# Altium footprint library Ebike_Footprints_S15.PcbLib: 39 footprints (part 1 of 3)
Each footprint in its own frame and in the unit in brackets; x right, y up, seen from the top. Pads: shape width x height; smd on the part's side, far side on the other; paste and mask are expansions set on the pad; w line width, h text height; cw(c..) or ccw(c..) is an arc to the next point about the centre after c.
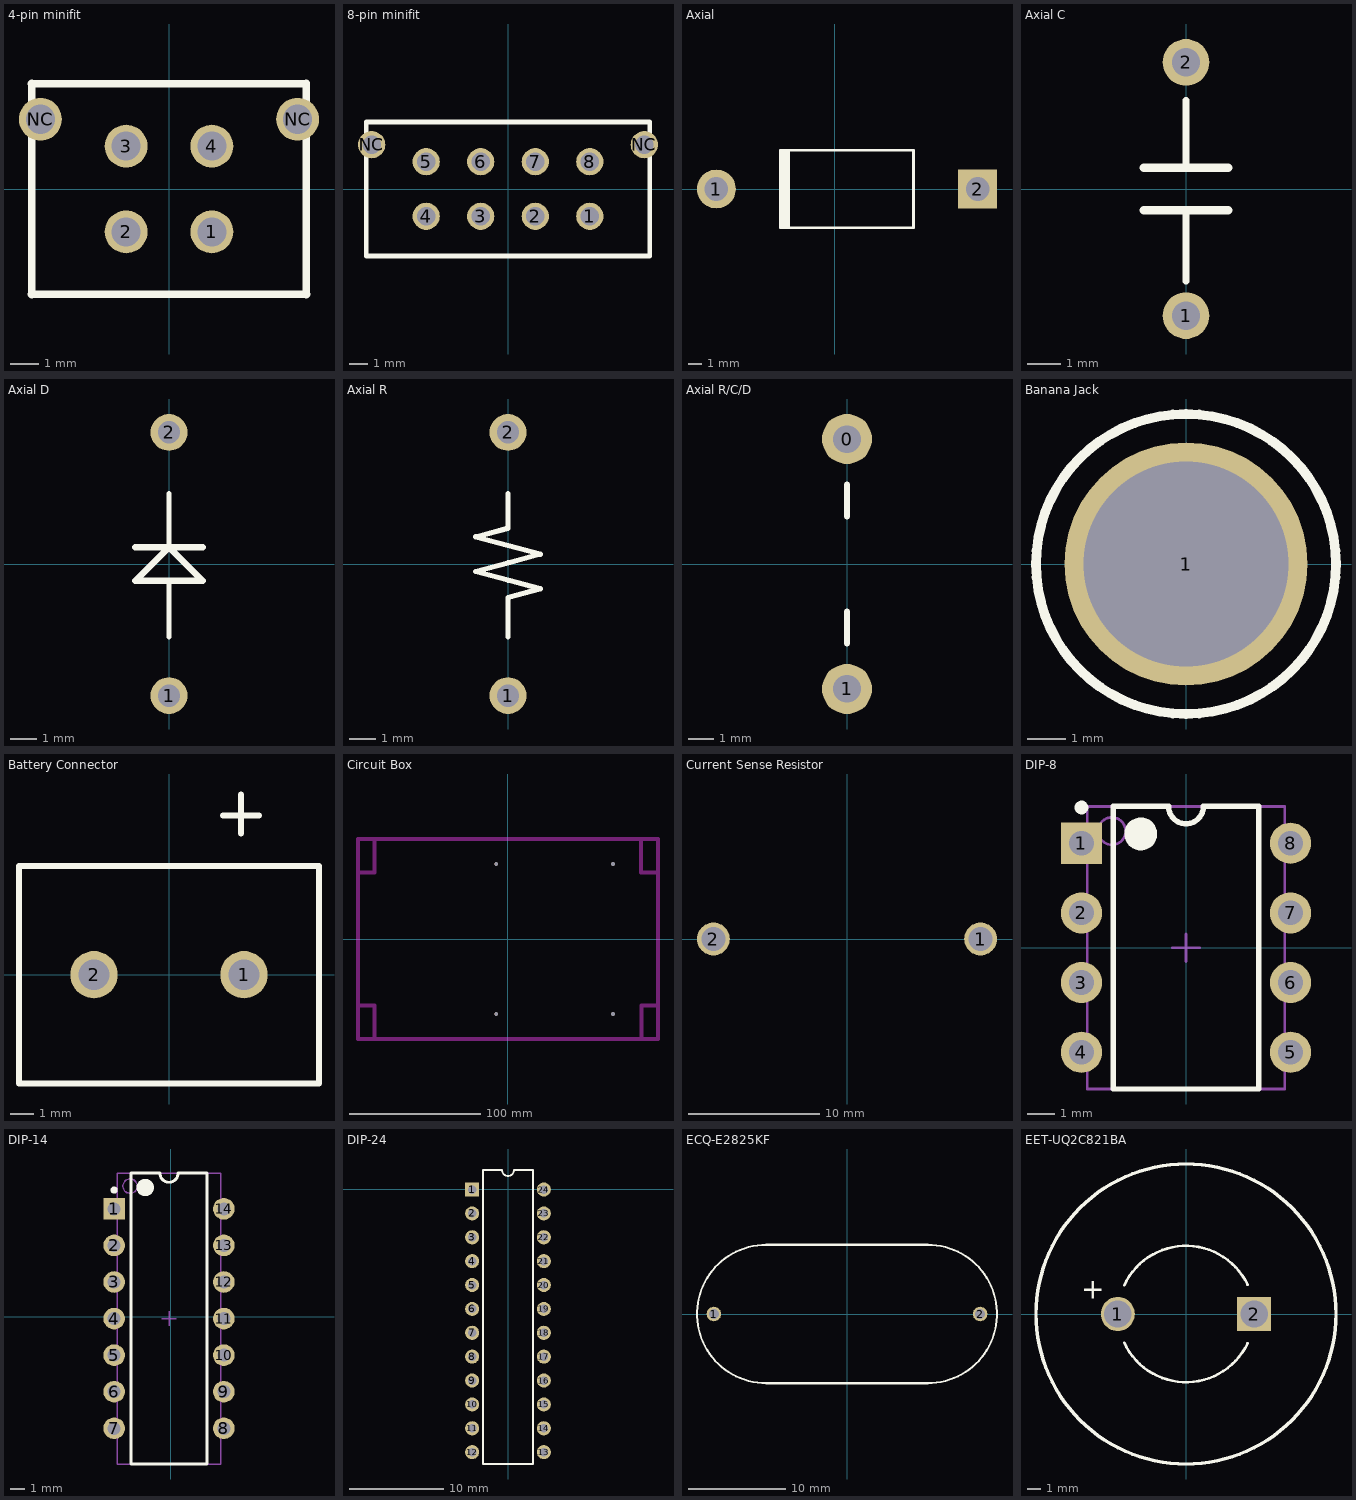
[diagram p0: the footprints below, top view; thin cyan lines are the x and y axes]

## 4-pin minifit [mm] "538-43045-0412   board connector straight"
pads (6):
  round 1.5 hole 1.02: 1(1.5,-1.5) 2(-1.5,-1.5) 3(-1.5,1.5) 4(1.5,1.5) NC(-4.5,2.44) NC(4.5,2.44)
Top Overlay:
  lines w0.254: -4.826,-3.683 4.826,-3.683 ; -4.826,3.683 4.699,3.683 ; -4.8,-3.7 -4.8,3.7 ; 4.8,-3.7 4.8,3.7
3D body: height 9.91, standoff 0, extent -4.826,-3.683 4.826,3.683

## 8-pin minifit [mm] "538-43045-0812   board connector straight"
pads (10):
  round 1.5 hole 1.02: 1(4.5,-1.5) 2(1.5,-1.5) 3(-1.5,-1.5) 4(-4.5,-1.5) 5(-4.5,1.5) 6(-1.5,1.5) 7(1.5,1.5) 8(4.5,1.5) NC(-7.5,2.44) NC(7.5,2.44)
Top Overlay:
  lines w0.254: -7.8,-3.7 -7.8,3.7 ; -7.747,-3.683 7.747,-3.683 ; -7.747,3.683 7.747,3.683 ; 7.8,-3.7 7.8,3.7
3D body: height 9.91, standoff 0, extent -7.747,-3.683 7.747,3.683

## Axial [mm]
pads (2):
  round 2.8 hole 1.7: 1(-8.531,0)
  rect 2.8x2.8 hole 1.7: 2(10.309,0)
Top Overlay:
  region: -3.211,2.8 -4.011,2.8 -4.011,-2.8 -3.211,-2.8
  lines w0.2: -3.911,-2.8 5.689,-2.8 5.689,2.8 -3.911,2.8

## Axial C [mm]
pads (2):
  round 1.4 hole 0.85: 1(0,-3.81) 2(0,3.81)
Top Overlay:
  lines w0.2: 0,-2.769 0,-0.635 ; 0,0.635 0,2.667
  lines w0.254: -1.27,-0.635 1.27,-0.635 ; -1.27,0.635 1.27,0.635
3D body: height 5, standoff -3, extent -1.116,-2.54 1.143,2.937

## Axial D [mm]
pads (2):
  round 1.4 hole 0.85: 1(0,-5) 2(0,5)
Top Overlay:
  lines w0.2: 0,-2.769 0,-0.635 ; 0,0.635 0,2.667
  lines w0.254: -1.27,0.635 1.27,0.635 ; -1.27,-0.635 1.27,-0.635 0,0.635 -1.27,-0.635
3D body: height 2.73, standoff -2.6, extent -1.343,-5.512 1.397,5.512

## Axial R [mm]
pads (2):
  round 1.4 hole 0.85: 1(0,-5) 2(0,5)
Top Overlay:
  lines w0.2: 0,-2.769 0,-1.27 1.227,-0.941 0,-0.613 -1.227,-0.284 0,0.045 1.227,0.373 0,0.702 -1.227,1.031 0,1.36 0,2.667
3D body: height 3.25, standoff -0.65, extent -1.27,-5.497 1.23,5.497

## Axial R/C/D [mm] "Through-Hole FootPrint"
pads (2):
  round 2 hole 1.1: 0(0,5) 1(0,-5)
Top Overlay:
  lines w0.254: 0,-3.175 0,-1.905 ; 0,1.905 0,3.175

## Banana Jack [mm] "575-8"
pads (1):
  round 6.4 hole 5.4: 1(0,0)
Top Overlay:
  circle w0.254: c0,0 r3.95
3D body: height 2.47, standoff 0.1, extent -2.59,-2.65 2.59,2.54
3D body: height 2.46, standoff 0.1, extent -3.932,-3.947 3.937,3.937
3D body: height 9, standoff 0.1, extent -2.59,-2.667 2.59,2.523

## Battery Connector [mm] "Phoenix 2-terminal Block Screw connector"
pads (2):
  round 2 hole 1.3: 1(3.175,0) 2(-3.175,0)
Top Overlay:
  lines w0.254: -6.35,-4.572 -6.35,4.572 ; -6.345,-4.6 6.345,-4.6 ; -6.345,4.6 6.345,4.6 ; 2.286,6.731 3.81,6.731 ; 3.048,5.969 3.048,7.62 ; 6.35,-4.572 6.35,4.572
3D body: height 15.2, standoff -3.5, extent -5,-4.301 5,4.699

## Circuit Box [mil] "Ebike mounted circuit box"
via 3155,-2255 diameter 118.11 hole 118.11
via 3155,2245 diameter 118.11 hole 118.11
via -350.39,2250 diameter 118.11 hole 118.11
via -350.39,-2250 diameter 118.11 hole 118.11
Keep-Out Layer:
  lines w118.11: -4500,-2000 -4000,-2000 -4000,-3000 ; -4500,2000 -4000,2000 -4000,3000 ; 4000,3000 4000,2000 4500,2000 ; 4005,-3000 4005,-2000 4505,-2000 ; 4500,2990 4500,-3000 -4500,-3000 -4500,3000 4500,3000
3D body: height 1062.99, standoff 0, extent 4455,-3020 4495,3015
3D body: height 1062.99, standoff 0, extent -4475,-3020 -4435,3015
3D body: height 1062.99, standoff 0, extent -4460,-3020 4475,-2980
3D body: height 1062.99, standoff 0, extent -4460,2975 4475,3015
3D body: height 1062.99, standoff 984.25, extent -4460,-3000 4475,2990

## Current Sense Resistor [mm] "Current Sense Resistor OAR5"
height 22.4
pads (2):
  round 2.5 hole 1.8: 1(10.16,0) 2(-10.16,0)

## DIP-8 [mm] "DIP; 8 Leads; Row Spacing 7.62 mm; Pitch 2.54 mm"
height 5.08
pads (8):
  rect 1.5x1.5 hole 0.9: 1(-3.81,3.81)
  round 1.5 hole 0.9: 2(-3.81,1.27) 3(-3.81,-1.27) 4(-3.81,-3.81) 5(3.81,-3.81) 6(3.81,-1.27) 7(3.81,1.27) 8(3.81,3.81)
Top Overlay:
  circle w0.6: c-1.65,4.15 r0.3
  circle w0.25: c-3.81,5.11 r0.125
  lines w0.2: -2.65,-5.15 2.65,-5.15 2.65,5.15 0.635,5.15 cw(c0,5.15) -0.635,5.15 -2.65,5.15 -2.65,-5.15
Mechanical 13:
  circle w0.1: c-2.7,4.25 r0.5
  lines w0.1: -3.6,-5.15 3.6,-5.15 3.6,5.15 -3.6,5.15 -3.6,-5.15
Mechanical 15:
  lines w0.1: -0.5,0 0.5,0 ; 0,-0.5 0,0.5
3D body: height 5.08, standoff 0, extent -3.6,-5.15 3.6,5.15

## DIP-14 [mm]
pads (14):
  rect 1.5x1.5 hole 0.9: 1(-3.937,7.493)
  round 1.5 hole 0.9: 2(-3.937,4.953) 3(-3.937,2.413) 4(-3.937,-0.127) 5(-3.937,-2.667) 6(-3.937,-5.207) 7(-3.937,-7.747) 8(3.683,-7.747) 9(3.683,-5.207) 10(3.683,-2.667) 11(3.683,-0.127) 12(3.683,2.413) 13(3.683,4.953) 14(3.683,7.493)
Top Overlay:
  circle w0.6: c-1.777,8.973 r0.3
  circle w0.25: c-3.937,8.793 r0.125
  lines w0.2: -2.777,-10.227 2.523,-10.227 2.523,9.973 0.508,9.973 cw(c-0.127,9.973) -0.762,9.973 -2.777,9.973 -2.777,-10.227
Mechanical 13:
  circle w0.1: c-2.827,9.073 r0.5
  lines w0.1: -3.727,-10.227 3.473,-10.227 3.473,9.973 -3.727,9.973 -3.727,-10.227
Mechanical 15:
  lines w0.1: -0.627,-0.127 0.373,-0.127 ; -0.127,-0.627 -0.127,0.373
3D body: height 5.08, standoff 0, extent -3.727,-10.227 3.473,9.973

## DIP-24 [mm]
pads (24):
  rect 1.5x1.5 hole 0.9: 1(-3.81,-0.01)
  round 1.5 hole 0.9: 2(-3.81,-2.55) 3(-3.81,-5.09) 4(-3.81,-7.63) 5(-3.81,-10.17) 6(-3.81,-12.71) 7(-3.81,-15.25) 8(-3.81,-17.79) 9(-3.81,-20.33) 10(-3.81,-22.87) 11(-3.81,-25.41) 12(-3.81,-27.95) 13(3.81,-27.95) 14(3.81,-25.41) 15(3.81,-22.87) 16(3.81,-20.33) 17(3.81,-17.79) 18(3.81,-15.25) 19(3.81,-12.71) 20(3.81,-10.17) 21(3.81,-7.63) 22(3.81,-5.09) 23(3.81,-2.55) 24(3.81,-0.01)
Top Overlay:
  lines w0.2: -2.667,-29.21 2.633,-29.21 ; -2.65,-29.21 -2.65,2.07 -0.635,2.07 ccw(c0,2.07) 0.635,2.07 2.65,2.07 2.65,-29.21
3D body: height 1.75, standoff 0.1, extent -3.683,-29.337 3.683,1.992

## ECQ-E2825KF [mm] "Thin Film Cap, 8.2uF 250V"
pads (2):
  round 1.5 hole 1: 1(-13.75,0) 2(13.75,0)
Top Overlay:
  lines w0.2: -8.35,-7.15 cw(c-8.35,0) -8.35,7.15 ; 8.35,-7.15 ccw(c8.35,0) 8.35,7.15
  lines w0.254: -8.35,-7.15 8.35,-7.15 ; -8.35,7.15 8.35,7.15
3D body: height 25, standoff 1.5, extent -8.382,-7.112 8.392,7.263
3D body: height 25, standoff 1.5, extent 1.27,-7.112 15.514,7.16
3D body: height 25, standoff 1.5, extent -15.621,-7.136 -1.377,7.136

## EET-UQ2C821BA [mm] "Electrolytic Cap"
pads (2):
  round 2.5 hole 2: 1(-5,0)
  rect 2.5x2.5 hole 2: 2(5,0)
Top Overlay:
  circle w0.254: c0,0 r11
  lines w0.2: -4.538,-2.1 ccw(c0,0) 4.514,-2.15 ; -4.538,2.1 cw(c0,0) 4.514,2.15
  text "+" at -5.969,2.413 h1.5
3D body: height 36, standoff 1, extent -10.913,-10.978 11,10.978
